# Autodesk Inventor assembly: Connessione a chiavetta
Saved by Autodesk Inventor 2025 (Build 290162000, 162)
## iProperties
Created: 2026-05
Part Number: Connessione a chiavetta
Document SubType Name: Assembly
Designer: Ryzen5700u
ClientObjectVersion: 1
Author: Ryzen5700u
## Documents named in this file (1)
- C:\Users\Ryzen5700u\Desktop\riduttore pompa\riduttore2\Design Accelerator\Connessione a chiavetta1.iam
